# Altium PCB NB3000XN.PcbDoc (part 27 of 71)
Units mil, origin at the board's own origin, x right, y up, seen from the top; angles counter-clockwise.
Board outline 9527.56 x 6929.77 mil, 6 copper layers (Top Layer, GND+SHIELD, MidLayer1, MidLayer2, P2 - 3V3+5V0, Bottom Layer), stack 62.375 mil thick; 832 components, 1027 nets, 4655 pads, 4981 vias.
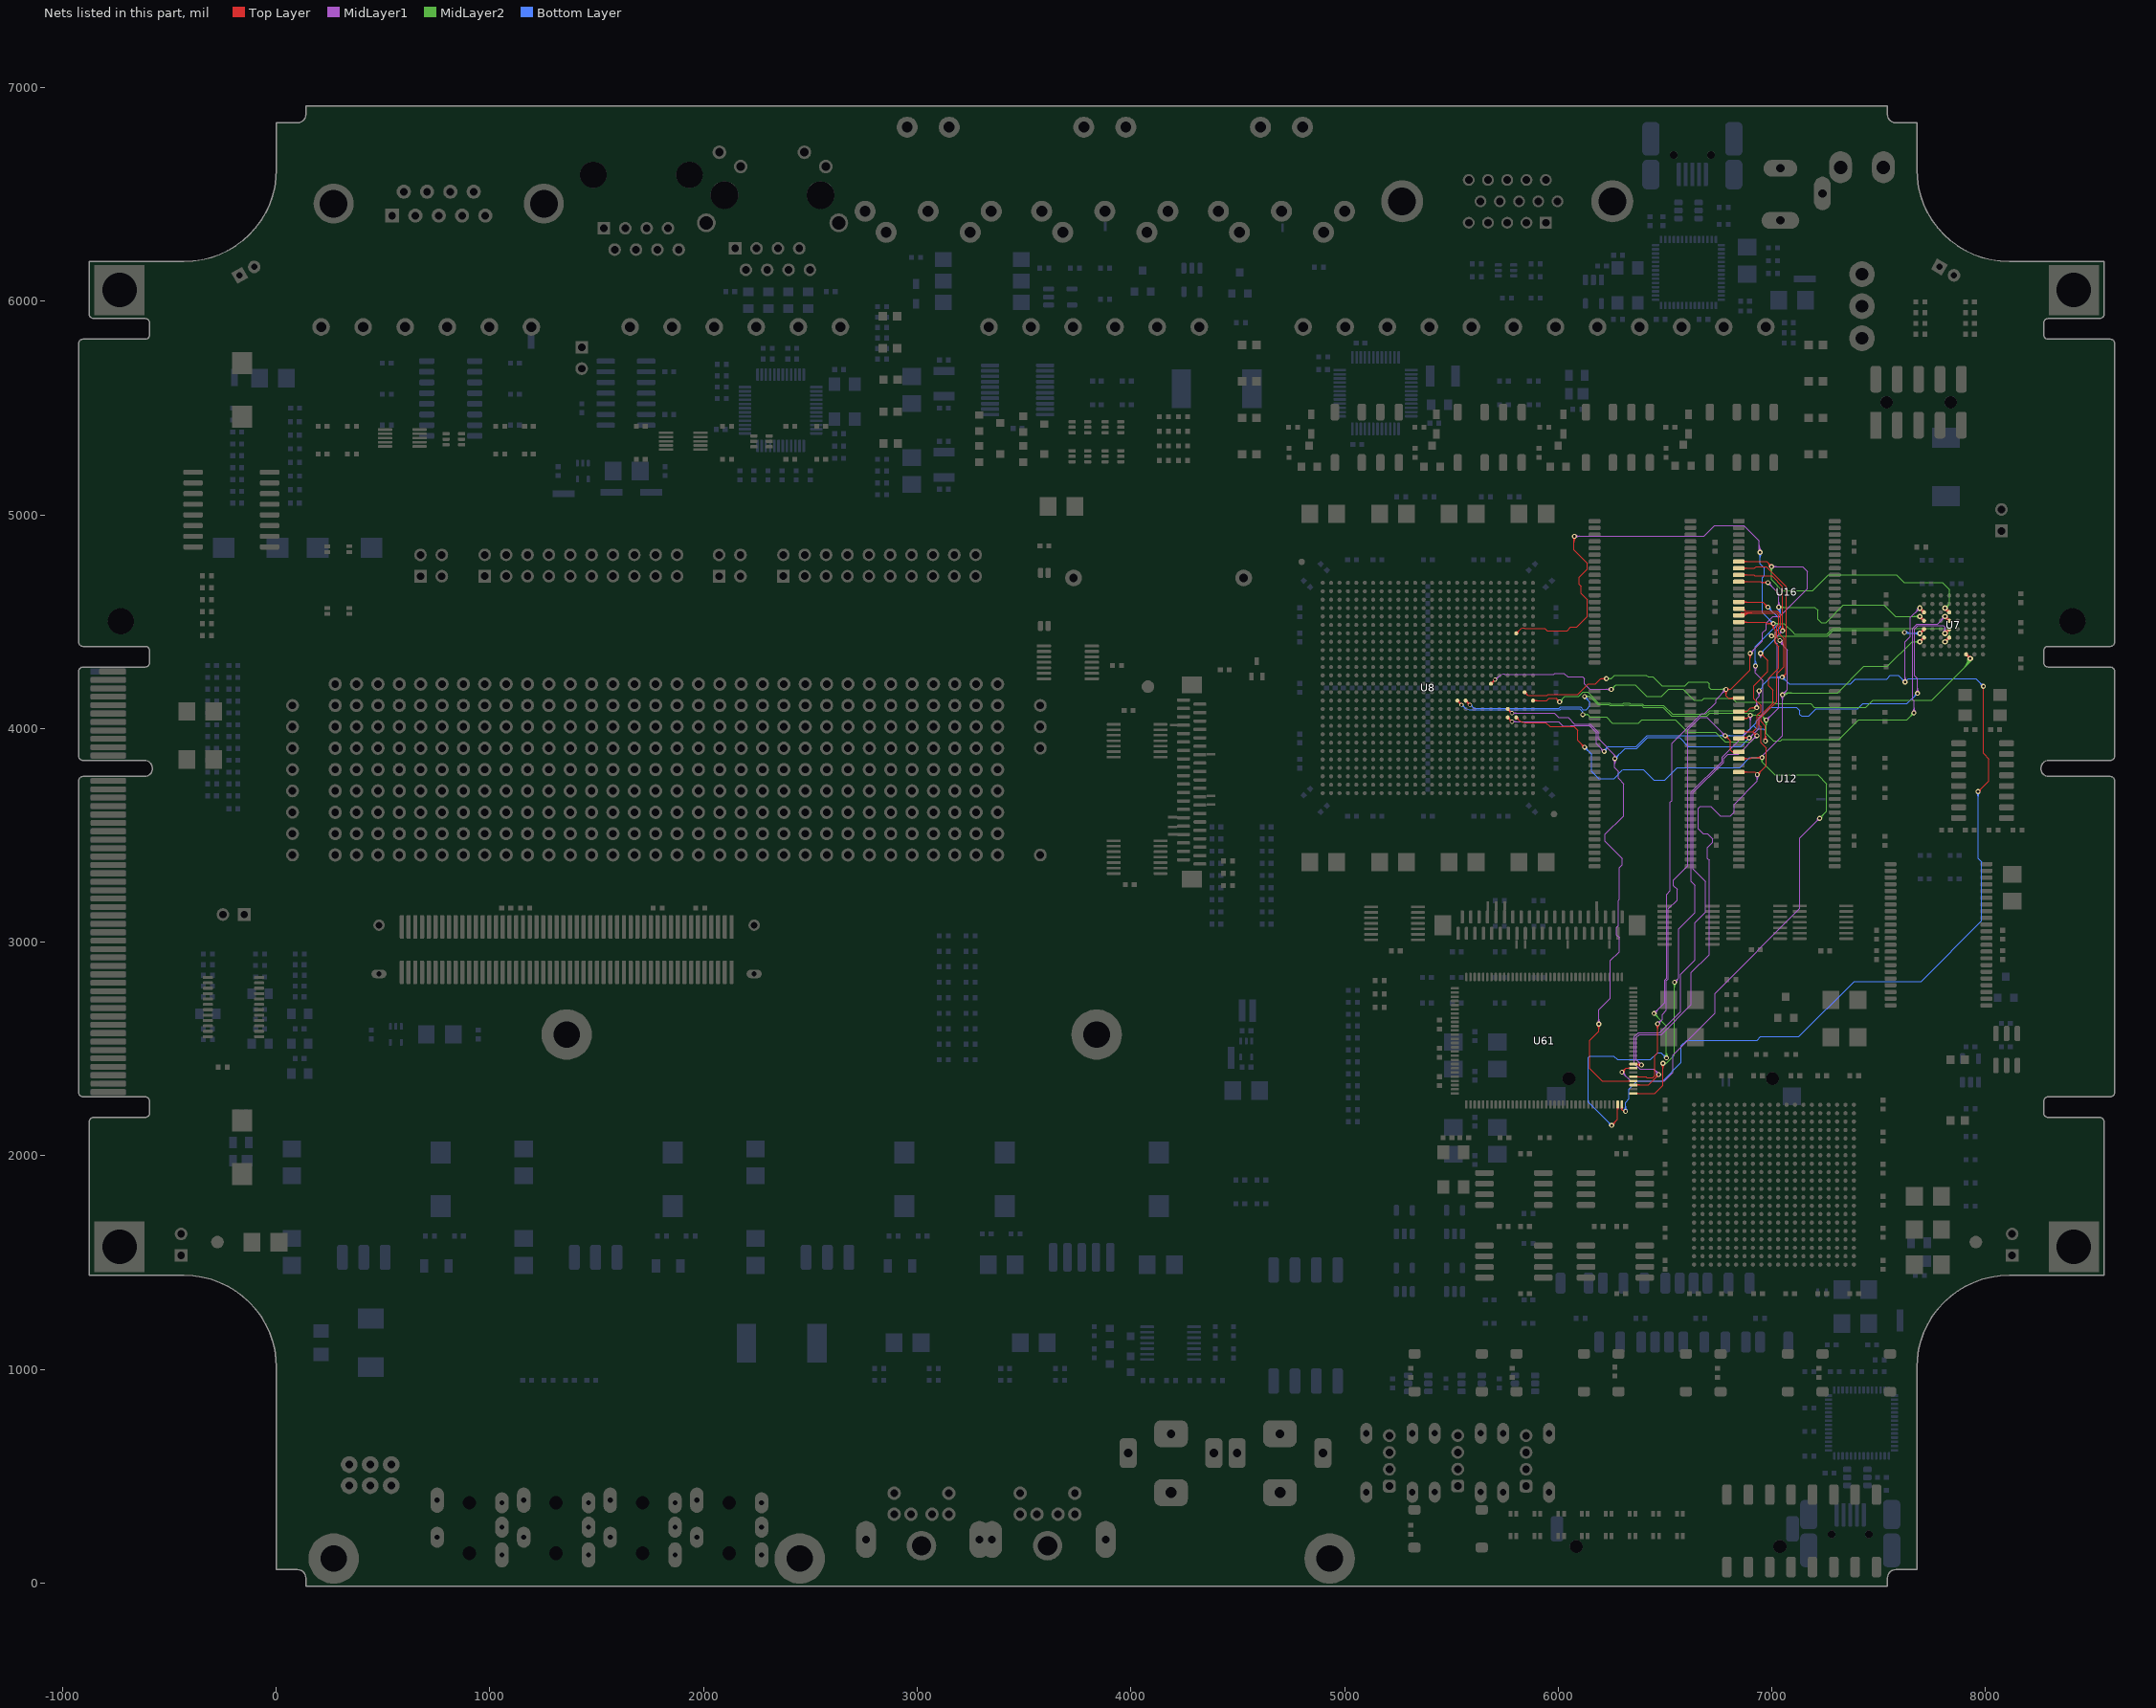
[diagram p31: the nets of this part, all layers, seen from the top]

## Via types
v1: diameter 23, hole 11.81, Top Layer to Bottom Layer, 3672 vias
v2: diameter 26, hole 11.81, Top Layer to Bottom Layer, 461 vias
v3: diameter 19, hole 11.81, Top Layer to Bottom Layer, tented both sides, 396 vias
v4: diameter 23.62, hole 11.81, Top Layer to Bottom Layer, 288 vias
v5: diameter 20, hole 11.81, Top Layer to Bottom Layer, 91 vias
v6: diameter 23, hole 11.81, Top Layer to Bottom Layer, tented both sides, 50 vias
v7: diameter 31, hole 11.81, Top Layer to Bottom Layer, 15 vias
v8: diameter 27.56, hole 11.81, Top Layer to Bottom Layer, tented both sides, 4 vias
v9: diameter 29, hole 11.81, Top Layer to Bottom Layer, 3 vias
v10: diameter 21, hole 11.81, Top Layer to Bottom Layer, 1 vias

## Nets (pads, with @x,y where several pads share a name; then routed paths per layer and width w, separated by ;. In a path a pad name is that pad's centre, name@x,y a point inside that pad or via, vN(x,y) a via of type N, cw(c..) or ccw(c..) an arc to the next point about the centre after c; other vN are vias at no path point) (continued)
DB_MEM.BUS_A24: U7.C8 U8.N21 | length 2990.7
  Top Layer w4: U8.N21@5685.28,4209.69 v3(5704.96,4229.37) ; U8.N21@5685.28,4217.03 ccw(c5685.28,4234.75) 5697.81,4222.22 ccw(c5710.34,4209.69) U8.N21@5692.62,4209.69 ; U8.N21@5685.28,4217.19 ccw(c5685.28,4235.29) 5698.08,4222.49 ccw(c5710.88,4209.69) U8.N21@5692.78,4209.69 ; 5692.16,4216.57 cw(c5704.96,4203.76) 5704.96,4221.87 ccw(c5704.96,4203.76) 5692.16,4216.57 ; 5692.16,4216.57 ccw(c5679.35,4229.37) 5697.46,4229.37 cw(c5679.35,4229.37) 5692.16,4216.57
  Top Layer w8: U7.C8@7909.06,4341.2 cw(c7909.06,4326.72) 7919.3,4336.96 cw(c7929.54,4347.2) U7.C8@7915.06,4347.2 ; U7.C8@7909.06,4347.2 v2(7928.74,4327.52) ; v2@7919.74,4327.52 ccw(c7898.01,4327.52) 7913.38,4342.88 ccw(c7928.74,4358.25) v2@7928.74,4336.52
  MidLayer1 w4: v3@5705.61,4236.84 ccw(c5707.19,4254.88) 5718.83,4241.01 ; v3@5712.43,4228.72 cw(c5730.47,4227.14) 5718.83,4241.01 ; 5781.77,4253.23 5767.84,4253.23 ; v1@6241.81,4176.66 ccw(c6225.59,4160.44) 6225.59,4183.37 ccw(c6225.59,4206.31) v1@6241.81,4190.09 ; v1@6244.64,4179.49 ccw(c6235.25,4170.1) 6235.25,4183.37 ccw(c6235.25,4196.65) v1@6244.64,4187.26 ; v1(6248.52,4183.37) 6148.52,4183.37 6123.52,4208.37 6123.52,4233.37 6115.19,4241.71 6044.19,4241.71 6027.52,4258.37 5985,4258.37 5979.86,4253.23 5920,4253.23 5910,4253.23 5861.38,4253.23 5841.96,4253.23 5767.84,4253.23 ; 5718.83,4241.01 cw(c5748.34,4211.5) 5748.34,4253.23 5767.84,4253.23
  MidLayer2 w4: v1(6248.52,4183.37) 6270.19,4205.04 6360.19,4205.04 6415.19,4150.04 6483.88,4150.04 6517.21,4183.37 6584.84,4183.37 6634.84,4133.37 6656.86,4133.37 6673.52,4133.37 6681.86,4141.71 6815.19,4141.71 6831.86,4125.04 7006.86,4125.04 7015.19,4116.71 7181.86,4116.71 7198.52,4100.04 7440.19,4100.04 7473.52,4133.37 7748.19,4133.37 7930.19,4315.37 7928.86,4316.71 7928.74,4316.71 v2(7928.74,4327.52) ; v1@6248.52,4188.87 ccw(c6248.52,4202.15) 6257.91,4192.76 ccw(c6267.3,4183.37) v1@6254.02,4183.37 ; v1@6248.52,4192.87 ccw(c6248.52,4215.81) 6264.74,4199.59 ccw(c6280.96,4183.37) v1@6258.02,4183.37 ; 7900.35,4285.53 ccw(c7858.36,4327.52) v2@7917.74,4327.52 ; 7907.18,4292.36 ccw(c7872.02,4327.52) v2@7921.74,4327.52 ; 7914.01,4299.19 ccw(c7885.68,4327.52) v2@7925.74,4327.52 ; 7920.83,4306.02 ccw(c7899.33,4327.52) v2@7929.74,4327.52 ; 7927.66,4312.85 ccw(c7912.99,4327.52) v2@7933.74,4327.52
DB_MEM.BUS_D0: U7.E3 U8.P25 U12.2 U16.7 U61.37 | length 7296.9
  Top Layer w4: U8.P25@5842.76,4162.97 cw(c5842.76,4145.25) 5855.29,4157.78 ; U8.P25@5850.1,4170.31 ccw(c5867.83,4170.31) 5855.29,4157.78 ; v1@6218.81,4226.66 ccw(c6202.59,4210.44) 6202.59,4233.37 ccw(c6202.59,4256.31) v1@6218.81,4240.09 ; v1@6221.64,4229.49 ccw(c6212.25,4220.1) 6212.25,4233.37 ccw(c6212.25,4246.65) v1@6221.64,4237.26 ; v1(6225.52,4233.37) 6198.52,4233.37 6173.52,4208.37 6141.52,4208.37 6092.52,4159.37 5953.04,4159.37 5948.47,4154.81 5920,4154.81 5910,4154.81 5862.47,4154.81 cw(c5862.47,4164.96) 5855.29,4157.78 ; v1(6250.52,2142.37) 6278.66,2170.51 U61.37@6278.66,2240 ; v1@6250.52,2147.87 ccw(c6250.52,2161.15) 6259.91,2151.76 ccw(c6269.3,2142.37) v1@6256.02,2142.37 ; v1@6250.52,2151.87 ccw(c6250.52,2174.81) 6266.74,2158.59 ccw(c6282.96,2142.37) v1@6260.02,2142.37 ; U61.37@6275.83,2223.98 cw(c6269,2217.15) 6278.66,2217.15 cw(c6288.32,2217.15) U61.37@6281.49,2223.98 ; v1@6778.47,4176.66 cw(c6762.26,4160.44) 6785.19,4160.44 cw(c6808.13,4160.44) v1@6791.91,4176.66 ; v1@6781.3,4179.49 cw(c6771.91,4170.1) 6785.19,4170.1 cw(c6798.47,4170.1) v1@6789.08,4179.49 ; v1@6789.11,4179.52 cw(c6798.31,4170.47) 6798.31,4183.37 cw(c6798.31,4196.28) v1@6789.11,4187.23 ; v1@6791.96,4176.71 cw(c6807.86,4161.09) 6807.86,4183.37 ; v1@6791.96,4190.04 ccw(c6807.86,4205.66) 6807.86,4183.37 ; U12.2@6822.37,4137.3 ccw(c6808.72,4123.64) 6808.72,4142.95 ccw(c6808.72,4162.27) U12.2@6822.37,4148.61 ; U12.2@6825.61,4142.95 U12.2@6845.59,4142.95 6796.05,4142.95 6785.19,4153.81 v1(6785.19,4183.37) 6807.86,4183.37 ; U16.7@6845.59,4781.73 6975.17,4781.73 v1(6998.52,4758.37) ; U16.7@6868.81,4776.08 cw(c6882.46,4762.42) 6882.46,4781.73 cw(c6882.46,4801.05) U16.7@6868.81,4787.39 ; v1@6891.81,4345.66 cw(c6875.59,4329.44) 6898.52,4329.44 cw(c6921.46,4329.44) v1@6905.24,4345.66 ; v1@6894.64,4348.49 cw(c6885.25,4339.1) 6898.52,4339.1 cw(c6911.8,4339.1) v1@6902.41,4348.49 ; v1(6898.52,4352.37) 6898.52,4274.04 6807.86,4183.37 ; v1@6989.02,4758.37 ccw(c6966.09,4758.37) 6982.31,4774.59 ccw(c6998.52,4790.81) v1@6998.52,4767.87 ; v1@6993.02,4758.37 ccw(c6979.75,4758.37) 6989.14,4767.76 ccw(c6998.52,4777.15) v1@6998.52,4763.87
  Top Layer w8: v2@7810.63,4554.74 cw(c7810.63,4533.01) 7825.99,4548.38 cw(c7841.36,4563.74) v2@7819.63,4563.74 ; v2(7810.63,4563.74) U7.E3@7830.32,4544.06 ; U7.E3@7824.32,4544.06 ccw(c7809.83,4544.06) 7820.07,4554.3 ccw(c7830.32,4564.54) U7.E3@7830.32,4550.06
  MidLayer1 w4: v1(6448.52,2666.71) 6498.52,2716.71 6498.52,2822.67 6507.19,2831.34 6507.19,3224.41 6523.52,3240.75 6523.52,3654.79 ; v1@6448.52,2672.21 ccw(c6448.52,2685.49) 6457.91,2676.1 ccw(c6467.3,2666.71) v1@6454.02,2666.71 ; v1@6448.52,2676.21 ccw(c6448.52,2699.14) 6464.74,2682.93 ccw(c6480.96,2666.71) v1@6458.02,2666.71 ; 6530,3661.26 6523.52,3654.79 ; v1@6775.69,4183.37 cw(c6752.76,4183.37) 6768.97,4167.16 cw(c6785.19,4150.94) v1@6785.19,4173.87 ; v1@6779.69,4183.37 cw(c6766.41,4183.37) 6775.8,4173.99 cw(c6785.19,4164.6) v1@6785.19,4177.87 ; v1(6785.19,4183.37) 6737.87,4136.06 6737.87,4122.72 6685.15,4070 6671.5,4070 6531.86,3930.36 6531.86,3663.12 6523.52,3654.79 ; v1(6898.52,4352.37) 6956.86,4410.71 6956.86,4448.37 6973.52,4465.04 6973.52,4492.71 7005.86,4525.04 7037.19,4525.04 7166.52,4654.37 7166.52,4735.37 7143.52,4758.37 v1(6998.52,4758.37) ; v1@6898.52,4357.87 ccw(c6898.52,4371.15) 6907.91,4361.76 ccw(c6917.3,4352.37) v1@6904.02,4352.37 ; v1@6898.52,4361.87 ccw(c6898.52,4384.81) 6914.74,4368.59 ccw(c6930.96,4352.37) v1@6908.02,4352.37 ; v1@7002.41,4754.49 cw(c7011.8,4745.1) 7011.8,4758.37 cw(c7011.8,4771.65) v1@7002.41,4762.26 ; v1@7005.24,4751.66 cw(c7021.46,4735.44) 7021.46,4758.37 cw(c7021.46,4781.31) v1@7005.24,4765.09
  MidLayer2 w4: v1(6225.52,4233.37) 6248.52,4233.37 6265.19,4250.04 6411.6,4250.04 6419.94,4241.71 6444.19,4241.71 6486.52,4199.37 6593.5,4199.37 6612.17,4218.04 6698.52,4218.04 6706.86,4209.71 6706.86,4191.71 6715.19,4183.37 v1(6785.19,4183.37) ; v1@6229.41,4229.49 cw(c6238.8,4220.1) 6238.8,4233.37 cw(c6238.8,4246.65) v1@6229.41,4237.26 ; v1@6232.24,4226.66 cw(c6248.46,4210.44) 6248.46,4233.37 cw(c6248.46,4256.31) v1@6232.24,4240.09 ; v1@6448.52,2657.21 cw(c6448.52,2634.27) 6464.74,2650.49 cw(c6480.96,2666.71) v1@6458.02,2666.71 ; v1@6448.52,2661.21 cw(c6448.52,2647.93) 6457.91,2657.32 cw(c6467.3,2666.71) v1@6454.02,2666.71 ; v1(6448.52,2666.71) 6506.86,2608.37 v1(6506.86,2458.37) ; v1@6500.14,2465.09 ccw(c6483.92,2481.31) 6506.86,2481.31 ccw(c6529.79,2481.31) v1@6513.57,2465.09 ; v1@6502.97,2462.26 ccw(c6493.58,2471.65) 6506.86,2471.65 ccw(c6520.14,2471.65) v1@6510.75,2462.26 ; v1@6778.47,4176.66 ccw(c6762.26,4160.44) 6762.26,4183.37 ccw(c6762.26,4206.31) v1@6778.47,4190.09 ; v1@6781.3,4179.49 ccw(c6771.91,4170.1) 6771.91,4183.37 ccw(c6771.91,4196.65) v1@6781.3,4187.26 ; v1@6991.81,4751.66 cw(c6975.59,4735.44) 6998.52,4735.44 cw(c7021.46,4735.44) v1@7005.24,4751.66 ; v1@6994.64,4754.49 cw(c6985.25,4745.1) 6998.52,4745.1 cw(c7011.8,4745.1) v1@7002.41,4754.49 ; v1(6998.52,4758.37) 6998.52,4696.48 7048.96,4646.04 7191.04,4646.04 7265,4720 7582.54,4720 7619.17,4683.37 7798.52,4683.37 7831.86,4650.04 7831.86,4584.97 7818.27,4571.37 7810.63,4571.37 v2(7810.63,4563.74) ; v2@7810.63,4570.74 ccw(c7810.63,4587.64) 7822.58,4575.69 ccw(c7834.53,4563.74) v2@7817.63,4563.74 ; v2@7810.63,4574.74 ccw(c7810.63,4601.3) 7829.41,4582.52 ccw(c7848.19,4563.74) v2@7821.63,4563.74
  Bottom Layer w4: v1@6241.02,2142.37 ccw(c6218.09,2142.37) 6234.31,2158.59 ccw(c6250.52,2174.81) v1@6250.52,2151.87 ; v1@6245.02,2142.37 ccw(c6231.75,2142.37) 6241.14,2151.76 ccw(c6250.52,2161.15) v1@6250.52,2147.87 ; v1(6250.52,2142.37) 6140.19,2252.71 6140.19,2395 6140.19,2400.04 6140.19,2460.19 6146.71,2466.71 6206.86,2466.71 6260.54,2466.71 6277.21,2450.04 6431.86,2450.04 6465.19,2483.37 6481.86,2483.37 v1(6506.86,2458.37) ; v1@6497.36,2458.37 ccw(c6474.42,2458.37) 6490.64,2474.59 ccw(c6506.86,2490.81) v1@6506.86,2467.87 ; v1@6501.36,2458.37 ccw(c6488.08,2458.37) 6497.47,2467.76 ccw(c6506.86,2477.15) v1@6506.86,2463.87
DB_MEM.BUS_D1: U7.H3 U8.R26 U12.4 U16.8 U61.38 | length 7924
  Top Layer w4: U8.R26@5882.13,4130.94 5910,4130.94 5920,4130.94 5947.24,4130.94 5958,4141.71 5990.19,4141.71 v1(6006.86,4125.04) ; U8.R26@5887.32,4125.75 cw(c5899.85,4113.22) 5899.85,4130.94 cw(c5899.85,4148.67) U8.R26@5887.32,4136.14 ; U8.R26@5887.43,4125.64 cw(c5900.23,4112.84) 5900.23,4130.94 cw(c5900.23,4149.05) U8.R26@5887.43,4136.25 ; v1@5997.36,4125.04 ccw(c5974.42,4125.04) 5990.64,4141.26 ccw(c6006.86,4157.48) v1@6006.86,4134.54 ; v1@6001.36,4125.04 ccw(c5988.08,4125.04) 5997.47,4134.43 ccw(c6006.86,4143.82) v1@6006.86,4130.54 ; U61.38@6295.52,2223.98 cw(c6288.69,2217.15) 6298.35,2217.15 cw(c6308,2217.15) U61.38@6301.17,2223.98 ; U61.38@6298.34,2240 6298.35,2216.37 6306.35,2208.37 v1(6315.19,2208.37) ; U12.4@6845.59,4079.96 6882.6,4079.96 6900.02,4097.37 v1(6929.52,4097.37) ; U16.8@6845.59,4750.24 6918.39,4750.24 6926.52,4758.37 6973.52,4758.37 7068.86,4663.04 7068.86,4433.37 7065.19,4429.71 7065.19,4257.37 v1(7048.52,4240.71) ; U12.4@6868.81,4074.3 cw(c6882.46,4060.65) 6882.46,4079.96 cw(c6882.46,4099.27) U12.4@6868.81,4085.62 ; U16.8@6868.81,4744.58 cw(c6882.46,4730.92) 6882.46,4750.24 cw(c6882.46,4769.55) U16.8@6868.81,4755.89 ; v1@6922.81,4090.66 ccw(c6906.59,4074.44) 6906.59,4097.37 ccw(c6906.59,4120.31) v1@6922.81,4104.09 ; v1@6925.64,4093.49 ccw(c6916.25,4084.1) 6916.25,4097.37 ccw(c6916.25,4110.65) v1@6925.64,4101.26 ; v1@7048.52,4246.21 ccw(c7048.52,4259.49) 7057.91,4250.1 ccw(c7067.3,4240.71) v1@7054.02,4240.71 ; v1@7048.52,4250.21 ccw(c7048.52,4273.14) 7064.74,4256.93 ccw(c7080.96,4240.71) v1@7058.02,4240.71 ; v1(7965.19,3705.37) 8015.19,3755.37 8015.19,3858.37 7990.19,3883.37 v1(7990.19,4198.04) ; v1@7965.19,3710.87 ccw(c7965.19,3724.15) 7974.58,3714.76 ccw(c7983.97,3705.37) v1@7970.69,3705.37 ; v1@7965.19,3714.87 ccw(c7965.19,3737.81) 7981.41,3721.59 ccw(c7997.63,3705.37) v1@7974.69,3705.37
  Top Layer w8: v2@7692.52,4554.74 cw(c7692.52,4533.01) 7707.88,4548.38 cw(c7723.25,4563.74) v2@7701.52,4563.74 ; v2(7692.52,4563.74) U7.H3@7712.2,4544.06 ; U7.H3@7706.2,4544.06 ccw(c7691.72,4544.06) 7701.96,4554.3 ccw(c7712.2,4564.54) U7.H3@7712.2,4550.06
  MidLayer1 w4: v1@6922.81,4104.09 ccw(c6906.59,4120.31) 6929.52,4120.31 ccw(c6952.46,4120.31) v1@6936.24,4104.09 ; v1@6925.64,4101.26 ccw(c6916.25,4110.65) 6929.52,4110.65 ccw(c6942.8,4110.65) v1@6933.41,4101.26 ; v1(6929.52,4097.37) 6929.52,4139.52 6940,4150 ; v1@6933.47,4169.99 cw(c6917.26,4153.77) 6940.19,4153.77 cw(c6963.13,4153.77) v1@6946.91,4169.99 ; v1@6936.3,4172.82 cw(c6926.91,4163.43) 6940.19,4163.43 cw(c6953.47,4163.43) v1@6944.08,4172.82 ; 6940.19,4150 v1(6940.19,4176.71) ; v1@7616.81,4224.43 ccw(c7600.59,4240.64) 7623.52,4240.64 ccw(c7646.46,4240.64) v1@7630.24,4224.43 ; v1@7619.64,4221.6 ccw(c7610.25,4230.99) 7623.52,4230.99 ccw(c7636.8,4230.99) v1@7627.41,4221.6 ; v1(7623.52,4217.71) 7623.52,4405.39 7648.52,4430.39 7648.52,4519.74 v2(7692.52,4563.74) ; v2@7681.52,4563.74 cw(c7654.96,4563.74) 7673.74,4544.96 cw(c7692.52,4526.19) v2@7692.52,4552.74 ; v2@7685.52,4563.74 cw(c7668.62,4563.74) 7680.57,4551.79 cw(c7692.52,4539.84) v2@7692.52,4556.74
  MidLayer2 w4: v1(6006.86,4125.04) 6031.86,4150.04 6095.52,4150.04 6115.48,4170 6138.23,4170 6188.52,4119.71 6241.48,4119.71 6245.82,4115.37 6302.56,4115.37 6306,4118.81 6334,4118.81 6337.44,4115.37 6394.5,4115.37 6401.5,4108.38 6493.16,4108.38 6534.17,4067.37 6692.86,4067.37 6708.86,4083.37 6915.52,4083.37 v1(6929.52,4097.37) ; v1@6006.86,4130.54 ccw(c6006.86,4143.82) 6016.25,4134.43 ccw(c6025.64,4125.04) v1@6012.36,4125.04 ; v1@6006.86,4134.54 ccw(c6006.86,4157.48) 6023.07,4141.26 ccw(c6039.29,4125.04) v1@6016.36,4125.04
  Bottom Layer w4: v1@6308.47,2215.09 ccw(c6292.26,2231.31) 6315.19,2231.31 ccw(c6338.13,2231.31) v1@6321.91,2215.09 ; v1@6311.3,2212.26 ccw(c6301.91,2221.65) 6315.19,2221.65 ccw(c6328.47,2221.65) v1@6319.08,2212.26 ; v1(6315.19,2208.37) 6315.19,2250 6332.19,2267 6332.19,2312.19 6370.04,2350.04 6489.58,2350.04 6576.18,2436.64 6576.18,2516.38 6601.51,2541.71 6930.52,2541.71 6947.19,2558.37 7126.86,2558.37 7385.19,2816.71 7698.52,2816.71 7981.86,3100.04 7981.86,3376.04 7965.19,3392.71 v1(7965.19,3705.37) ; v1(6940.19,4176.71) 6955.75,4192.27 6955.75,4202.62 6993.84,4240.71 v1(7048.52,4240.71) 7080.86,4208.37 7367.54,4208.37 7391.54,4232.37 7537.33,4232.37 7555,4250.04 7591.19,4250.04 v1(7623.52,4217.71) 7639.19,4233.37 7954.86,4233.37 v1(7990.19,4198.04) ; v1@7041.81,4233.99 ccw(c7025.59,4217.77) 7025.59,4240.71 ccw(c7025.59,4263.64) v1@7041.81,4247.43 ; v1@7044.64,4236.82 ccw(c7035.25,4227.43) 7035.25,4240.71 ccw(c7035.25,4253.99) v1@7044.64,4244.6 ; v1@7048.52,4231.21 cw(c7048.52,4208.27) 7064.74,4224.49 cw(c7080.96,4240.71) v1@7058.02,4240.71 ; v1@7048.52,4235.21 cw(c7048.52,4221.93) 7057.91,4231.32 cw(c7067.3,4240.71) v1@7054.02,4240.71 ; v1@7614.02,4217.71 ccw(c7591.09,4217.71) 7607.31,4233.93 ccw(c7623.52,4250.14) v1@7623.52,4227.21 ; v1@7618.02,4217.71 ccw(c7604.75,4217.71) 7614.13,4227.1 ccw(c7623.52,4236.49) v1@7623.52,4223.21 ; v1@7958.47,3698.66 cw(c7942.26,3682.44) 7965.19,3682.44 cw(c7988.13,3682.44) v1@7971.91,3698.66 ; v1@7961.3,3701.49 cw(c7951.91,3692.1) 7965.19,3692.1 cw(c7978.47,3692.1) v1@7969.08,3701.49 ; v1@7980.69,4198.04 ccw(c7957.76,4198.04) 7973.97,4214.26 ccw(c7990.19,4230.48) v1@7990.19,4207.54 ; v1@7984.69,4198.04 ccw(c7971.41,4198.04) 7980.8,4207.43 ccw(c7990.19,4216.82) v1@7990.19,4203.54
DB_MEM.BUS_D2: U7.E4 U8.R18 U12.5 U16.9 U61.39 | length 7174.9
  Top Layer w4: U8.R18@5567.17,4123.44 cw(c5567.17,4105.34) 5579.97,4118.14 cw(c5592.77,4130.94) U8.R18@5574.67,4130.94 ; U8.R18@5567.17,4123.6 cw(c5567.17,4105.88) 5579.7,4118.41 cw(c5592.23,4130.94) U8.R18@5574.51,4130.94 ; U8.R18@5567.17,4130.94 v3(5586.85,4111.26) ; U61.39@6351.93,2291.98 6451.19,2291.98 6490.19,2330.98 v1(6490.19,2433.37) ; U61.39@6367.95,2289.15 cw(c6374.78,2282.32) 6374.78,2291.98 cw(c6374.78,2301.63) U61.39@6367.95,2294.8 ; v1@6483.47,2426.66 cw(c6467.26,2410.44) 6490.19,2410.44 cw(c6513.13,2410.44) v1@6496.91,2426.66 ; v1@6486.3,2429.49 cw(c6476.91,2420.1) 6490.19,2420.1 cw(c6503.47,2420.1) v1@6494.08,2429.49 ; U12.5@6845.59,4048.46 6885.28,4048.46 v1(6899.19,4062.37) ; U16.9@6845.59,4718.74 6915.52,4718.74 6919.52,4714.74 7000.49,4714.74 7050.86,4664.37 v1(7050.86,4458.37) ; U12.5@6868.81,4042.81 cw(c6882.46,4029.15) 6882.46,4048.46 cw(c6882.47,4067.78) U12.5@6868.81,4054.12 ; U16.9@6868.81,4713.08 cw(c6882.46,4699.43) 6882.46,4718.74 cw(c6882.46,4738.05) U16.9@6868.81,4724.4 ; v1@7044.14,4465.09 ccw(c7027.92,4481.31) 7050.86,4481.31 ccw(c7073.79,4481.31) v1@7057.57,4465.09 ; v1@7046.97,4462.26 ccw(c7037.58,4471.65) 7050.86,4471.65 ccw(c7064.14,4471.65) v1@7054.75,4462.26 ; 5574.05,4124.06 cw(c5561.24,4111.26) 5579.35,4111.26 ccw(c5561.24,4111.26) 5574.05,4124.06 ; 5574.05,4124.06 ccw(c5586.85,4136.87) 5586.85,4118.76 cw(c5586.85,4136.87) 5574.05,4124.06
  Top Layer w8: v2@7810.63,4515.37 cw(c7810.63,4493.64) 7825.99,4509.01 cw(c7841.36,4524.37) v2@7819.63,4524.37 ; v2(7810.63,4524.37) U7.E4@7830.32,4504.69 ; U7.E4@7824.32,4504.69 ccw(c7809.83,4504.69) 7820.07,4514.93 ccw(c7830.32,4525.17) U7.E4@7830.32,4510.69
  MidLayer1 w4: v1(6544.86,2813.04) 6561.71,2829.89 6564.86,2833.04 6564.86,3063 6640.19,3138.33 6640.19,3266.71 6623.52,3283.37 6623.52,3702.67 6767,3846.15 6767,3867 6899.19,3999.19 v1(6899.19,4062.37) ; v1@6544.86,2818.54 ccw(c6544.86,2831.82) 6554.25,2822.43 ccw(c6563.64,2813.04) v1@6550.36,2813.04 ; v1@6544.86,2822.54 ccw(c6544.86,2845.48) 6561.07,2829.26 ccw(c6577.29,2813.04) v1@6554.36,2813.04 ; v1@6892.47,4055.66 cw(c6876.26,4039.44) 6899.19,4039.44 cw(c6922.13,4039.44) v1@6905.91,4055.66 ; v1@6895.3,4058.49 cw(c6885.91,4049.1) 6899.19,4049.1 cw(c6912.47,4049.1) v1@6903.08,4058.49 ; v1(6973.52,4039.71) 7031.86,4098.04 7031.86,4233.37 7025.19,4240.04 7025.19,4396.04 7015.19,4406.04 7015.19,4422.71 v1(7050.86,4458.37) ; v1@6973.52,4045.21 ccw(c6973.52,4058.49) 6982.91,4049.1 ccw(c6992.3,4039.71) v1@6979.02,4039.71 ; v1@6973.52,4049.21 ccw(c6973.52,4072.14) 6989.74,4055.93 ccw(c7005.96,4039.71) v1@6983.02,4039.71 ; v1@7041.36,4458.37 cw(c7018.42,4458.37) 7034.64,4442.16 cw(c7050.86,4425.94) v1@7050.86,4448.87 ; v1@7045.36,4458.37 cw(c7032.08,4458.37) 7041.47,4448.99 cw(c7050.86,4439.6) v1@7050.86,4452.87 ; v1@7658.47,4080.09 ccw(c7642.26,4096.31) 7665.19,4096.31 ccw(c7688.13,4096.31) v1@7671.91,4080.09 ; v1@7661.3,4077.26 ccw(c7651.91,4086.65) 7665.19,4086.65 ccw(c7678.47,4086.65) v1@7669.08,4077.26 ; v1(7665.19,4073.37) 7665.19,4129.81 7660,4135 7660,4469.85 7679.97,4489.82 7776.08,4489.82 v2(7810.63,4524.37) ; v2@7799.63,4524.37 cw(c7773.07,4524.37) 7791.85,4505.59 cw(c7810.63,4486.82) v2@7810.63,4513.37 ; v2@7803.63,4524.37 cw(c7786.73,4524.37) 7798.68,4512.42 cw(c7810.63,4500.47) v2@7810.63,4517.37
  MidLayer2 w4: v1(6123.52,4150.04) 6146.88,4150.04 6185.21,4111.71 6238.17,4111.71 6242.5,4107.37 6305.87,4107.37 6309.31,4110.81 6330.69,4110.81 6334.13,4107.37 6391.19,4107.37 6398.18,4100.38 6489.85,4100.38 6530.86,4059.37 6697.19,4059.37 6709.86,4072.04 6889.52,4072.04 v1(6899.19,4062.37) 6950.86,4062.37 v1(6973.52,4039.71) 6973.52,3975.04 7006.86,3941.71 7040.19,3941.71 7048.52,3950.04 7314.58,3950.04 7405.92,4041.37 7633.19,4041.37 7641.86,4050.04 v1(7665.19,4073.37) ; v1@6127.41,4146.15 cw(c6136.8,4136.76) 6136.8,4150.04 cw(c6136.8,4163.32) v1@6127.41,4153.93 ; v1@6130.24,4143.32 cw(c6146.46,4127.11) 6146.46,4150.04 cw(c6146.46,4172.98) v1@6130.24,4156.76 ; v1(6490.19,2433.37) 6506.86,2433.37 ; v1@6498.36,2428.53 cw(c6506.86,2423.51) 6506.86,2433.37 ; v1@6498.36,2438.22 ccw(c6506.86,2443.24) 6506.86,2433.37 ; v1@6538.14,2806.32 cw(c6521.92,2790.11) 6544.86,2790.11 cw(c6567.79,2790.11) v1@6551.57,2806.32 ; v1@6540.97,2809.15 cw(c6531.58,2799.76) 6544.86,2799.76 cw(c6558.14,2799.76) v1@6548.75,2809.15 ; v1(6544.86,2813.04) 6544.86,2471.37 6506.86,2433.37 ; v1@6903.08,4058.49 cw(c6912.47,4049.1) 6912.47,4062.37 cw(c6912.47,4075.65) v1@6903.08,4066.26 ; v1@6905.91,4055.66 cw(c6922.13,4039.44) 6922.13,4062.37 cw(c6922.13,4085.31) v1@6905.91,4069.09 ; v1@6964.02,4039.71 ccw(c6941.09,4039.71) 6957.31,4055.93 ccw(c6973.52,4072.14) v1@6973.52,4049.21 ; v1@6966.81,4032.99 cw(c6950.59,4016.77) 6973.52,4016.77 cw(c6996.46,4016.77) v1@6980.24,4032.99 ; v1@6968.02,4039.71 ccw(c6954.75,4039.71) 6964.14,4049.1 ccw(c6973.52,4058.49) v1@6973.52,4045.21 ; v1@6969.64,4035.82 cw(c6960.25,4026.43) 6973.52,4026.43 cw(c6986.8,4026.43) v1@6977.41,4035.82 ; v1@7655.69,4073.37 cw(c7632.76,4073.37) 7648.97,4057.16 cw(c7665.19,4040.94) v1@7665.19,4063.87 ; v1@7659.69,4073.37 cw(c7646.41,4073.37) 7655.8,4063.99 cw(c7665.19,4054.6) v1@7665.19,4067.87
  Bottom Layer w4: v3@5587.5,4103.79 cw(c5589.08,4085.75) 5600.72,4099.62 cw(c5612.36,4113.49) v3@5594.32,4111.91 ; 5600.43,4099.87 ccw(c5610.36,4109.8) 5610.36,4095.75 5703.9,4095.75 5910,4095.75 5920,4095.75 6005.15,4095.75 6010.21,4100.81 6105.09,4100.81 6116.87,4089.02 6131.84,4089.02 6133.58,4090.77 6148.52,4105.71 6148.52,4125.04 v1(6123.52,4150.04) ; v1@6123.52,4140.54 cw(c6123.52,4117.61) 6139.74,4133.82 cw(c6155.96,4150.04) v1@6133.02,4150.04 ; v1@6123.52,4144.54 cw(c6123.52,4131.26) 6132.91,4140.65 cw(c6142.3,4150.04) v1@6129.02,4150.04
DB_MEM.BUS_D3: U7.H4 U8.R17 U12.7 U16.10 U61.41 | length 6741.8
  Top Layer w4: U8.R17@5527.8,4123.44 cw(c5527.8,4105.34) 5540.6,4118.14 cw(c5553.4,4130.94) U8.R17@5535.3,4130.94 ; U8.R17@5527.8,4123.6 cw(c5527.8,4105.88) 5540.33,4118.41 cw(c5552.86,4130.94) U8.R17@5535.14,4130.94 ; U8.R17@5527.8,4130.94 v3(5547.48,4111.26) ; U61.41@6356.86,2333.37 6423.52,2333.37 v1(6470.52,2380.37) ; U61.41@6367.95,2328.52 cw(c6379.68,2316.79) 6379.68,2333.37 ; v1@6461.02,2380.37 cw(c6438.09,2380.37) 6454.31,2364.16 cw(c6470.52,2347.94) v1@6470.52,2370.87 ; v1@6465.02,2380.37 cw(c6451.75,2380.37) 6461.14,2370.99 cw(c6470.52,2361.6) v1@6470.52,2374.87 ; U12.7@6845.59,3985.47 6911.52,3985.47 ; U16.10@6845.59,4687.24 6946.66,4687.24 6950.52,4683.37 v1(6981.86,4683.37) ; U12.7@6868.81,3979.82 cw(c6882.46,3966.16) 6882.46,3985.47 cw(c6882.46,4004.79) U12.7@6868.81,3991.13 ; U16.10@6868.81,4681.59 cw(c6882.46,4667.93) 6882.46,4687.24 cw(c6882.46,4706.56) U16.10@6868.81,4692.9 ; 6913.9,3983.09 cw(c6897.52,3966.71) v1@6920.69,3966.71 ; 6914.14,3982.86 ccw(c6930.19,3998.91) v1@6930.19,3976.21 ; v1@6930.19,3966.8 6911.52,3985.47 ; v1@6947.19,4342.87 cw(c6947.19,4319.94) 6963.41,4336.16 cw(c6979.63,4352.37) v1@6956.69,4352.37 ; v1@6947.19,4346.87 cw(c6947.19,4333.6) 6956.58,4342.99 cw(c6965.97,4352.37) v1@6952.69,4352.37 ; v1(6947.19,4352.37) 6981.86,4317.71 6981.86,4266.71 6915.19,4200.04 6915.19,4140.71 6948.52,4107.37 6948.52,4079.71 6931.86,4063.04 6931.86,4005.8 6911.52,3985.47 ; v1@6975.14,4676.66 ccw(c6958.92,4660.44) 6958.92,4683.37 ccw(c6958.92,4706.31) v1@6975.14,4690.09 ; v1@6977.97,4679.49 ccw(c6968.58,4670.1) 6968.58,4683.37 ccw(c6968.58,4696.65) v1@6977.97,4687.26 ; 5534.68,4124.06 cw(c5521.87,4111.26) 5539.98,4111.26 ccw(c5521.87,4111.26) 5534.68,4124.06 ; 5534.68,4124.06 ccw(c5547.48,4136.87) 5547.48,4118.76 cw(c5547.48,4136.87) 5534.68,4124.06 ; 6920.73,3976.26 cw(c6911.18,3966.71) 6924.69,3966.71 ccw(c6911.18,3966.71) 6920.73,3976.26 ; 6920.97,3976.03 ccw(c6930.19,3985.25) 6930.19,3972.21 cw(c6930.19,3985.25) 6920.97,3976.03
  Top Layer w8: v2@7692.52,4515.37 cw(c7692.52,4493.64) 7707.88,4509.01 cw(c7723.25,4524.37) v2@7701.52,4524.37 ; v2(7692.52,4524.37) U7.H4@7712.2,4504.69 ; U7.H4@7706.2,4504.69 ccw(c7691.72,4504.69) 7701.96,4514.93 ccw(c7712.2,4525.17) U7.H4@7712.2,4510.69
  MidLayer1 w4: 6451.01,2404.56 cw(c6426.82,2380.37) v1@6461.02,2380.37 ; 6457.84,2397.73 cw(c6440.48,2380.37) v1@6465.02,2380.37 ; 6462.27,2393.29 ccw(c6470.52,2401.55) v1@6470.52,2389.87 ; 6464.66,2390.9 cw(c6454.14,2380.37) v1@6469.02,2380.37 ; v1@6470.52,2385.04 6448.52,2407.04 6381.86,2407.04 6356.86,2432.04 6356.86,2557.56 6375,2575.71 6474.19,2575.71 6573.52,2675.04 6573.52,2850.04 6640.19,2916.71 6640.19,3091.71 6690.19,3141.71 6690.19,3283.37 6631.86,3341.71 6631.86,3699.69 6775,3842.83 6775,3860 6795,3880 6843.48,3880 v1(6930.19,3966.71) ; v1@6920.69,3966.71 cw(c6897.76,3966.71) 6913.97,3950.49 cw(c6930.19,3934.27) v1@6930.19,3957.21 ; v1@6924.69,3966.71 cw(c6911.41,3966.71) 6920.8,3957.32 cw(c6930.19,3947.93) v1@6930.19,3961.21 ; v1@6941.14,4345.05 cw(c6930.5,4332.19) 6947.19,4332.19 cw(c6963.88,4332.19) v1@6953.24,4345.05 ; v1@6943.69,4348.14 cw(c6937.53,4340.69) 6947.19,4340.69 cw(c6956.85,4340.69) v1@6950.7,4348.14 ; v1@6981.86,4673.87 cw(c6981.86,4650.94) 6998.07,4667.16 cw(c7014.29,4683.37) v1@6991.36,4683.37 ; v1@6981.86,4677.87 cw(c6981.86,4664.6) 6991.25,4673.99 cw(c7000.64,4683.37) v1@6987.36,4683.37 ; v1(6981.86,4683.37) 7032.52,4632.71 v1(7032.52,4568.37) ; v1@7025.81,4575.09 ccw(c7009.59,4591.31) 7032.52,4591.31 ccw(c7055.46,4591.31) v1@7039.24,4575.09 ; v1@7028.64,4572.26 ccw(c7019.25,4581.65) 7032.52,4581.65 ccw(c7045.8,4581.65) v1@7036.41,4572.26
  MidLayer2 w4: v1(6115,4065) 6138.37,4065 6148.37,4055 6225.23,4055 6253.85,4026.37 6375.88,4026.37 6390.88,4041.37 6510,4041.37 6518.63,4041.37 6548.63,4041.37 6565,4025 6606.96,3983.04 6736.96,3983.04 6782,3938 6901.48,3938 v1(6930.19,3966.71) ; v1@6118.89,4061.11 cw(c6128.28,4051.72) 6128.28,4065 cw(c6128.28,4078.28) v1@6118.89,4068.89 ; v1@6121.72,4058.28 cw(c6137.93,4042.06) 6137.93,4065 cw(c6137.93,4087.93) v1@6121.72,4071.72 ; v1@6920.69,3966.71 cw(c6897.76,3966.71) 6913.97,3950.49 cw(c6930.19,3934.27) v1@6930.19,3957.21 ; v1@6924.69,3966.71 cw(c6911.41,3966.71) 6920.8,3957.32 cw(c6930.19,3947.93) v1@6930.19,3961.21 ; v1(7032.52,4568.37) 7199.86,4568.37 7215.19,4553.04 7215.19,4512.04 7231.86,4495.37 7253.19,4495.37 7335.52,4577.71 7524.61,4577.71 7577.94,4524.37 v2(7692.52,4524.37) ; v1@7036.41,4564.49 cw(c7045.8,4555.1) 7045.8,4568.37 cw(c7045.8,4581.65) v1@7036.41,4572.26 ; v1@7039.24,4561.66 cw(c7055.46,4545.44) 7055.46,4568.37 cw(c7055.46,4591.31) v1@7039.24,4575.09 ; v2@7684.74,4516.59 ccw(c7665.96,4497.82) 7665.96,4524.37 ccw(c7665.96,4550.93) v2@7684.74,4532.15 ; v2@7687.57,4519.42 ccw(c7675.62,4507.47) 7675.62,4524.37 ccw(c7675.62,4541.27) v2@7687.57,4529.32
  Bottom Layer w4: v3@5548.13,4103.79 cw(c5549.71,4085.75) 5561.35,4099.62 ; v3@5554.95,4111.91 ccw(c5572.99,4113.49) 5561.35,4099.62 ; v1(6115,4065) 6115,4079.59 6101.77,4092.81 6013.53,4092.81 6008.11,4087.4 5924.74,4087.4 5920,4087.4 5910,4087.4 5703.9,4087.4 5684.48,4087.4 5610.36,4087.4 5590.86,4087.4 cw(c5590.86,4129.13) 5561.35,4099.62 ; v1(6947.19,4352.37) 7016.19,4421.37 7016.19,4451.04 7040.19,4475.04 7040.19,4560.71 v1(7032.52,4568.37) ; v1@6947.19,4357.87 ccw(c6947.19,4371.15) 6956.58,4361.76 ccw(c6965.97,4352.37) v1@6952.69,4352.37 ; v1@6947.19,4361.87 ccw(c6947.19,4384.81) 6963.41,4368.59 ccw(c6979.63,4352.37) v1@6956.69,4352.37 ; v1@7025.81,4561.66 cw(c6991.08,4526.93) 7040.19,4526.93 ; v1@7028.64,4564.49 cw(c7000.74,4536.59) 7040.19,4536.59 ; v1@7031.46,4567.31 cw(c7010.4,4546.25) 7040.19,4546.25 ; v1@7034.29,4570.14 cw(c7020.05,4555.9) 7040.19,4555.9
DB_MEM.BUS_D4: U7.H5 U8.T23 U12.8 U16.13 U61.42 | length 6009.3
  Top Layer w4: U8.T23@5764.02,4084.07 cw(c5764.02,4065.97) 5776.82,4078.77 cw(c5789.62,4091.57) U8.T23@5771.52,4091.57 ; U8.T23@5764.02,4084.23 cw(c5764.02,4066.51) 5776.55,4079.04 cw(c5789.08,4091.57) U8.T23@5771.36,4091.57 ; U8.T23@5764.02,4091.57 v3(5783.7,4071.89) ; v1@6183.47,2609.99 cw(c6167.26,2593.77) 6190.19,2593.77 cw(c6213.13,2593.77) v1@6196.91,2609.99 ; v1@6186.3,2612.82 cw(c6176.91,2603.43) 6190.19,2603.43 cw(c6203.47,2603.43) v1@6194.08,2612.82 ; v1(6190.19,2616.71) 6190.19,2583.37 6148.52,2541.71 6148.52,2408.37 6205.87,2351.03 U61.42@6351.49,2351.03 ; U61.42@6335.91,2348.2 ccw(c6329.08,2341.37) 6329.08,2351.03 ccw(c6329.08,2360.69) U61.42@6335.91,2353.86 ; U12.8@6845.59,3953.98 6856.86,3953.98 6856.86,3958.37 v1@6891.52,3958.37 ; U16.13@6845.59,4592.76 6957.48,4592.76 v1(6981.86,4568.37) ; U12.8@6863.15,3953.98 cw(c6873.22,3944.66) 6873.22,3958.37 ; U12.8@6864.82,3958.37 cw(c6864.82,3926.33) v1@6887.47,3948.99 ; U12.8@6866.08,3951.26 cw(c6882.37,3936.18) 6882.37,3958.37 ; U16.13@6868.81,4587.1 cw(c6882.46,4573.44) 6882.46,4592.76 cw(c6882.46,4612.07) U16.13@6868.81,4598.41 ; U12.8@6869.02,3948.54 cw(c6891.52,3927.71) v1@6891.52,3958.37 ; 6874.47,3958.37 cw(c6874.47,3935.99) v1@6890.3,3951.82 ; 6877.69,3958.37 ccw(c6877.69,3972.2) v1@6887.47,3962.43 ; v1(6894.19,3955.71) v1@6891.52,3958.37 ; v1@6972.36,4568.37 ccw(c6949.42,4568.37) 6965.64,4584.59 ccw(c6981.86,4600.81) v1@6981.86,4577.87 ; v1@6976.36,4568.37 ccw(c6963.08,4568.37) 6972.47,4577.76 ccw(c6981.86,4587.15) v1@6981.86,4573.87 ; 5770.9,4084.69 cw(c5758.09,4071.89) 5776.2,4071.89 ccw(c5758.09,4071.89) 5770.9,4084.69 ; 5770.9,4084.69 ccw(c5783.7,4097.5) 5783.7,4079.39 cw(c5783.7,4097.5) 5770.9,4084.69
  Top Layer w8: v2(7692.52,4445.63) U7.H5@7712.2,4465.32 ; v2@7692.52,4454.63 ccw(c7692.52,4476.36) 7707.88,4460.99 ccw(c7723.25,4445.63) v2@7701.52,4445.63 ; U7.H5@7706.2,4465.32 cw(c7691.72,4465.32) 7701.96,4455.07 cw(c7712.2,4444.83) U7.H5@7712.2,4459.32
  MidLayer1 w4: v3(5783.7,4071.89) 5861.38,4071.89 5910,4071.89 5920,4071.89 5924.74,4071.89 5981.86,4071.89 5990.19,4063.56 6001.25,4052.5 6046.42,4052.5 6077.04,4021.87 6149.44,4021.87 6187.62,3983.7 6187.62,3953.28 6265.19,3875.71 ; v3@5788.89,4066.7 cw(c5801.43,4054.16) 5801.43,4071.89 cw(c5801.43,4089.62) v3@5788.89,4077.08 ; v3@5789,4066.59 cw(c5801.81,4053.78) 5801.81,4071.89 cw(c5801.81,4090) v3@5789,4077.19 ; v1@6183.47,2623.43 ccw(c6167.26,2639.64) 6190.19,2639.64 ccw(c6213.13,2639.64) v1@6196.91,2623.43 ; v1@6186.3,2620.6 ccw(c6176.91,2629.99) 6190.19,2629.99 ccw(c6203.47,2629.99) v1@6194.08,2620.6 ; v1(6190.19,2616.71) 6190.19,2683.37 6244.86,2738.04 6244.86,2914.02 6285.86,2955.02 6285.86,3022.04 6273.52,3034.37 6273.52,3069.69 6281.19,3077.35 6281.19,3195.02 6285,3198.83 6287.19,3201.02 6287.19,3349.71 6299.52,3362.04 6299.52,3391.71 6220,3471.23 6220,3504.85 6306.43,3591.28 6306.86,3591.71 6306.86,3742.02 6281.86,3767.02 6281.86,3800.04 6265.19,3816.71 v1(6265.19,3859.04) 6265.19,3875.71 ; v1@6258.47,3852.32 cw(c6242.26,3836.11) 6265.19,3836.11 cw(c6288.13,3836.11) v1@6271.91,3852.32 ; v1@6260.35,3867.22 ccw(c6255.32,3875.71) 6265.19,3875.71 ; v1@6261.3,3855.15 cw(c6251.91,3845.76) 6265.19,3845.76 cw(c6278.47,3845.76) v1@6269.08,3855.15 ; v1@6270.03,3867.22 cw(c6275.06,3875.71) 6265.19,3875.71 ; v1(6894.19,3955.71) 6940.19,4001.71 6940.19,4052.35 6958.86,4071.02 6958.86,4224.37 6923.52,4259.71 v1(6923.52,4293.04) ; v1@6894.19,3961.21 ccw(c6894.19,3974.49) 6903.58,3965.1 ccw(c6912.97,3955.71) v1@6899.69,3955.71 ; v1@6894.19,3965.21 ccw(c6894.19,3988.14) 6910.41,3971.93 ccw(c6926.63,3955.71) v1@6903.69,3955.71 ; v1@6916.81,4286.32 cw(c6900.59,4270.11) 6923.52,4270.11 cw(c6946.46,4270.11) v1@6930.24,4286.32 ; v1@6919.64,4289.15 cw(c6910.25,4279.76) 6923.52,4279.76 cw(c6936.8,4279.76) v1@6927.41,4289.15
  MidLayer2 w4: v1(6998.52,4433.37) 7261.47,4433.37 7287.8,4459.71 7333.19,4459.71 7611.19,4459.71 v1(7620.86,4450.04) ; v1@7002.41,4429.49 cw(c7011.8,4420.1) 7011.8,4433.37 cw(c7011.8,4446.65) v1@7002.41,4437.26 ; v1@7005.24,4426.66 cw(c7021.46,4410.44) 7021.46,4433.37 cw(c7021.46,4456.31) v1@7005.24,4440.09
  Bottom Layer w4: v1(6265.19,3859.04) 6313.52,3907.37 6368.17,3907.37 6419.5,3958.71 6567.84,3958.71 6609.84,3916.71 6855.19,3916.71 v1(6894.19,3955.71) ; v1@6265.19,3864.54 ccw(c6265.19,3877.82) 6274.58,3868.43 ccw(c6283.97,3859.04) v1@6270.69,3859.04 ; v1@6265.19,3868.54 ccw(c6265.19,3891.48) 6281.41,3875.26 ccw(c6297.63,3859.04) v1@6274.69,3859.04 ; v1@6884.69,3955.71 cw(c6861.76,3955.71) 6877.97,3939.49 cw(c6894.19,3923.27) v1@6894.19,3946.21 ; v1@6888.69,3955.71 cw(c6875.41,3955.71) 6884.8,3946.32 cw(c6894.19,3936.93) v1@6894.19,3950.21 ; v1@6916.81,4299.76 ccw(c6900.59,4315.98) 6923.52,4315.98 ccw(c6946.46,4315.98) v1@6930.24,4299.76 ; v1@6919.64,4296.93 ccw(c6910.25,4306.32) 6923.52,4306.32 ccw(c6936.8,4306.32) v1@6927.41,4296.93 ; v1(6923.52,4293.04) 6923.52,4383.37 6986.02,4445.87 ; v1@6981.86,4558.87 cw(c6981.86,4535.94) 6998.07,4552.16 cw(c7014.29,4568.37) v1@6991.36,4568.37 ; v1@6981.86,4562.87 cw(c6981.86,4549.6) 6991.25,4558.99 cw(c7000.64,4568.37) v1@6987.36,4568.37 ; v1(6981.86,4568.37) 7031.86,4518.37 7031.86,4491.71 6986.02,4445.87 ; v1(6998.52,4433.37) 6986.02,4445.87 ; v1(7620.86,4450.04) 7628.19,4450.04 7632.6,4445.63 v2(7692.52,4445.63) ; v1@7621.92,4451.1 ccw(c7635.13,4464.31) 7635.13,4445.63 ; v1@7624.75,4453.93 ccw(c7644.78,4473.97) 7644.78,4445.63 ; v1@7627.57,4443.32 cw(c7633.14,4437.75) 7633.14,4445.63 ; v1@7627.57,4456.76 ccw(c7654.44,4483.62) 7654.44,4445.63 ; v2@7684.74,4437.85 ccw(c7665.96,4419.07) 7665.96,4445.63 ccw(c7665.96,4472.19) v2@7684.74,4453.41 ; v2@7687.57,4440.68 ccw(c7675.62,4428.73) 7675.62,4445.63 ccw(c7675.62,4462.53) v2@7687.57,4450.58
DB_MEM.BUS_D5: U7.E5 U8.U23 U12.10 U16.14 U61.43 | length 6965.3
  Top Layer w4: U8.U23@5764.02,4044.7 cw(c5764.02,4026.6) 5776.82,4039.4 cw(c5789.62,4052.2) U8.U23@5771.52,4052.2 ; U8.U23@5764.02,4044.86 cw(c5764.02,4027.14) 5776.55,4039.67 cw(c5789.08,4052.2) U8.U23@5771.36,4052.2 ; U8.U23@5764.02,4052.2 v3(5783.7,4032.52) ; U61.43@6351.93,2370.72 6411.18,2370.72 6415.19,2366.71 6442.86,2366.71 6452.19,2376.04 6452.19,2470 6465.19,2483 v1(6465.19,2617.71) ; U61.43@6367.95,2367.89 cw(c6374.78,2361.06) 6374.78,2370.72 cw(c6374.78,2380.37) U61.43@6367.95,2373.54 ; v1@6458.47,2610.99 cw(c6442.26,2594.77) 6465.19,2594.77 cw(c6488.13,2594.77) v1@6471.91,2610.99 ; v1@6461.3,2613.82 cw(c6451.91,2604.43) 6465.19,2604.43 cw(c6478.47,2604.43) v1@6469.08,2613.82 ; v1@6781.86,3957.21 cw(c6781.86,3934.27) 6798.07,3950.49 cw(c6814.29,3966.71) v1@6791.36,3966.71 ; v1@6781.86,3961.21 cw(c6781.86,3947.93) 6791.25,3957.32 cw(c6800.64,3966.71) v1@6787.36,3966.71 ; v1(6781.86,3966.71) 6806.86,3941.71 6806.86,3898.98 6814.86,3890.98 ; U12.10@6820.93,3887.29 ccw(c6814.86,3884.14) 6814.86,3890.98 ; U12.10@6820.93,3894.67 cw(c6814.86,3897.83) 6814.86,3890.98 ; U12.10@6845.59,3890.98 6814.86,3890.98 ; U16.14@6845.59,4561.26 6863.15,4561.26 6875.7,4548.71 ; U16.14@6863.64,4553.27 cw(c6864.6,4537.61) 6875.7,4548.71 ; U16.14@6871.13,4560.77 ccw(c6886.78,4559.8) 6875.7,4548.71 ; v1@6963.47,3948.43 ccw(c6947.26,3964.64) 6970.19,3964.64 ccw(c6993.13,3964.64) v1@6976.91,3948.43 ; v1@6966.3,3945.6 ccw(c6956.91,3954.99) 6970.19,3954.99 ccw(c6983.47,3954.99) v1@6974.08,3945.6 ; v1(6970.19,3941.71) 6970.19,4011.71 6948.52,4033.37 6948.52,4051.37 7023.52,4126.37 7023.52,4257.04 7056.86,4290.37 7056.86,4421.37 7032.19,4446.04 7032.19,4475.37 7040.19,4483.37 7040.19,4533.37 7024.86,4548.71 6875.7,4548.71 ; 5770.9,4045.32 cw(c5758.09,4032.52) 5776.2,4032.52 ccw(c5758.09,4032.52) 5770.9,4045.32 ; 5770.9,4045.32 ccw(c5783.7,4058.13) 5783.7,4040.02 cw(c5783.7,4058.13) 5770.9,4045.32
  Top Layer w8: v2(7810.63,4445.63) U7.E5@7830.32,4465.32 ; v2@7810.63,4454.63 ccw(c7810.63,4476.36) 7825.99,4460.99 ccw(c7841.36,4445.63) v2@7819.63,4445.63 ; U7.E5@7824.32,4465.32 cw(c7809.83,4465.32) 7820.07,4455.07 cw(c7830.32,4444.83) U7.E5@7830.32,4459.32
  MidLayer1 w4: v3(5783.7,4032.52) 5861.38,4032.52 5910,4032.52 5920,4032.52 6002.73,4032.52 6022.75,4012.5 6060,4012.5 6061.37,4013.87 6146.13,4013.87 6179.62,3980.38 6179.62,3928.28 v1(6215.19,3892.71) ; v3@5788.89,4027.33 cw(c5801.43,4014.79) 5801.43,4032.52 cw(c5801.43,4050.25) v3@5788.89,4037.71 ; v1@6205.69,3892.71 ccw(c6182.76,3892.71) 6198.97,3908.93 ccw(c6215.19,3925.14) v1@6215.19,3902.21 ; v1@6209.69,3892.71 ccw(c6196.41,3892.71) 6205.8,3902.1 ccw(c6215.19,3911.49) v1@6215.19,3898.21 ; v1(6465.19,2617.71) 6487.19,2639.71 6487.19,2662.38 6506.86,2682.05 6506.86,2819.69 6515.19,2828.02 6515.19,3155.71 6556.86,3197.37 6556.86,3247.37 6540.19,3264.04 6540.19,3291.71 6606.86,3358.37 6606.86,3994.04 6664.19,4051.37 6697.19,4051.37 v1(6781.86,3966.71) ; v1@6465.19,2623.21 ccw(c6465.19,2636.49) 6474.58,2627.1 ccw(c6483.97,2617.71) v1@6470.69,2617.71 ; v1@6465.19,2627.21 ccw(c6465.19,2650.14) 6481.41,2633.93 ccw(c6497.63,2617.71) v1@6474.69,2617.71 ; v1@6772.36,3966.71 ccw(c6749.42,3966.71) 6765.64,3982.93 ccw(c6781.86,3999.14) v1@6781.86,3976.21 ; v1@6776.36,3966.71 ccw(c6763.08,3966.71) 6772.47,3976.1 ccw(c6781.86,3985.49) v1@6781.86,3972.21 ; v1@7675.14,4171.76 ccw(c7658.92,4187.98) 7681.86,4187.98 ccw(c7704.79,4187.98) v1@7688.57,4171.76 ; v1@7677.97,4168.93 ccw(c7668.58,4178.32) 7681.86,4178.32 ccw(c7695.14,4178.32) v1@7685.75,4168.93 ; v1(7681.86,4165.04) 7681.86,4233.14 7668,4247 7668,4466.54 7683.28,4481.82 7803.18,4481.82 7810.63,4474.37 v2(7810.63,4445.63) ; v2@7802.85,4453.41 ccw(c7784.07,4472.19) 7810.63,4472.19 ccw(c7837.19,4472.19) v2@7818.41,4453.41 ; v2@7805.68,4450.58 ccw(c7793.73,4462.53) 7810.63,4462.53 ccw(c7827.53,4462.53) v2@7815.58,4450.58 ; 5801.81,4032.52 cw(c5801.81,4050.63) 5789,4037.82 ccw(c5801.81,4050.63) 5801.81,4032.52 ; 5801.81,4032.52 ccw(c5801.81,4014.41) 5789,4027.22 cw(c5801.81,4014.41) 5801.81,4032.52
  Bottom Layer w4: v1(6215.19,3892.71) 6215.19,3898.71 6231.86,3915.37 ; v1@6215.19,3902.21 ccw(c6215.19,3910.66) 6221.17,3904.68 ; v1@6216.68,3892.91 cw(c6229.69,3894.64) 6220.41,3903.93 ; v1@6220.64,3893.43 cw(c6239.8,3895.99) 6226.13,3909.65 ; v1@6224.61,3893.96 cw(c6249.9,3897.33) 6231.86,3915.37 ; v1@6775.14,3959.99 ccw(c6758.92,3943.77) 6758.92,3966.71 ccw(c6758.92,3989.64) v1@6775.14,3973.43 ; v1@6777.97,3962.82 ccw(c6768.58,3953.43) 6768.58,3966.71 ccw(c6768.58,3979.99) v1@6777.97,3970.6 ; v1@6785.75,3962.82 cw(c6795.14,3953.43) 6795.14,3966.71 cw(c6795.14,3979.99) v1@6785.75,3970.6 ; v1@6788.57,3959.99 cw(c6804.79,3943.77) 6804.79,3966.71 cw(c6804.79,3989.64) v1@6788.57,3973.43 ; v1@6963.47,3948.43 ccw(c6947.26,3964.64) 6970.19,3964.64 ccw(c6993.13,3964.64) v1@6976.91,3948.43 ; v1@6966.3,3945.6 ccw(c6956.91,3954.99) 6970.19,3954.99 ccw(c6983.47,3954.99) v1@6974.08,3945.6 ; v1(6970.19,3941.71) 6970.19,3990.19 6961.37,3999.01 6929.56,3999.01 6913.52,4015.04 6865.19,3966.71 ; v1@7672.36,4165.04 cw(c7649.42,4165.04) 7665.64,4148.82 cw(c7681.86,4132.61) v1@7681.86,4155.54 ; v1@7676.36,4165.04 cw(c7663.08,4165.04) 7672.47,4155.65 cw(c7681.86,4146.26) v1@7681.86,4159.54 ; v1(7681.86,4165.04) 7633.52,4116.71 7426.51,4116.71 7401.51,4091.71 7206.86,4091.71 7173.52,4058.37 7140.19,4058.37 7131.86,4066.71 7131.86,4083.37 7114.86,4100.37 6993.5,4100.37 6926.82,4033.69 6926.82,4028.34 6865.19,3966.71 ; 6231.86,3915.37 6364.86,3915.37 6416.19,3966.71 v1(6781.86,3966.71) 6865.19,3966.71
DB_MEM.BUS_D6: U7.H6 U8.U24 U12.11 U16.15 U61.45 | length 6808.1
  Top Layer w4: v1@6114.02,3912.71 ccw(c6091.09,3912.71) 6107.31,3928.93 ccw(c6123.52,3945.14) v1@6123.52,3922.21 ; v1@6118.02,3912.71 ccw(c6104.75,3912.71) 6114.14,3922.1 ccw(c6123.52,3931.49) v1@6123.52,3918.21 ; v1(6123.52,3912.71) 6092.5,3943.73 6092.5,3990.73 6091.19,3992.04 6073.52,4009.71 5989,4009.71 5960.88,4009.71 5942.24,4028.34 5940.19,4028.34 5924.74,4028.34 5920,4028.34 5910,4028.34 5843.27,4028.34 ; v1(6298.52,2391.71) 6316.9,2410.09 U61.45@6351.93,2410.09 ; v1@6298.52,2397.21 ccw(c6298.52,2410.49) 6307.91,2401.1 ccw(c6317.3,2391.71) v1@6304.02,2391.71 ; v1@6298.52,2401.21 ccw(c6298.52,2424.14) 6314.74,2407.93 ccw(c6330.96,2391.71) v1@6308.02,2391.71 ; U61.45@6335.91,2407.26 ccw(c6329.08,2400.43) 6329.08,2410.09 ccw(c6329.08,2419.74) U61.45@6335.91,2412.91 ; U12.11@6845.59,3859.49 6900,3859.49 6905.22,3864.71 v1(6954.52,3864.71) v1@6948.19,3858.37 ; U16.15@6845.59,4529.76 6848.52,4529.76 6858.8,4540.04 7022.21,4540.04 7032.19,4530.06 7032.19,4486.69 7024.19,4478.69 7024.19,4425.71 v1(7037.86,4412.04) ; U16.15@6854.66,4538.25 cw(c6858.99,4533.92) 6858.99,4540.04 ; U16.15@6857.49,4535.42 cw(c6868.65,4524.27) 6868.65,4540.04 ; U16.15@6860.32,4532.59 cw(c6878.3,4514.61) 6878.3,4540.04 ; U16.15@6863.15,4529.76 cw(c6887.96,4504.95) 6887.96,4540.04 ; U16.15@6865.98,4526.94 cw(c6897.62,4495.3) 6897.62,4540.04 ; U12.11@6868.81,3853.83 cw(c6882.46,3840.18) 6882.46,3859.49 cw(c6882.46,3878.8) U12.11@6868.81,3865.15 ; U16.15@6868.81,4524.11 cw(c6907.27,4485.64) 6907.27,4540.04 ; v1@6947.81,3857.99 ccw(c6931.59,3841.77) 6931.59,3864.71 ccw(c6931.59,3887.64) v1@6947.81,3871.43 ; v1@6950.64,3860.82 ccw(c6941.25,3851.43) 6941.25,3864.71 ccw(c6941.25,3877.99) v1@6950.64,3868.6 ; 5815.92,4039.67 ccw(c5843.27,4067.02) 5843.27,4028.34 ; 5815.92,4039.67 ccw(c5843.27,4067.02) 5843.27,4028.34 ; 5815.92,4039.67 cw(c5828.45,4052.2) 5810.73,4052.2 ccw(c5828.45,4052.2) 5815.92,4039.67 ; 5815.92,4039.67 ccw(c5803.39,4027.14) 5803.39,4044.86 cw(c5803.39,4027.14) 5815.92,4039.67
  Top Layer w8: v2(7692.52,4406.26) U7.H6@7712.2,4425.94 ; v2@7692.52,4415.26 ccw(c7692.52,4436.99) 7707.88,4421.62 ccw(c7723.25,4406.26) v2@7701.52,4406.26 ; U7.H6@7706.2,4425.94 cw(c7691.72,4425.94) 7701.96,4415.7 cw(c7712.2,4405.46) U7.H6@7712.2,4419.94
  MidLayer1 w4: v1@6298.52,2382.21 cw(c6298.52,2359.27) 6314.74,2375.49 cw(c6330.96,2391.71) v1@6308.02,2391.71 ; v1@6298.52,2386.21 cw(c6298.52,2372.93) 6307.91,2382.32 cw(c6317.3,2391.71) v1@6304.02,2391.71 ; v1(6298.52,2391.71) 6340.19,2350.04 6497.19,2350.04 6537.19,2390.04 6537.19,2472.04 6733.86,2668.71 6733.86,2760.37 7131.86,3158.37 7131.86,3488.04 v1(7223.52,3579.71) ; v1(6954.52,3864.71) 6954.52,3871.71 7049.52,3966.71 v1(7049.52,4158.04) 7073.52,4182.04 7073.52,4368.04 7029.52,4412.04 v1(7037.86,4412.04) ; v1@7039.36,4412.04 ccw(c7063.1,4412.04) 7046.31,4395.25 ; v1@7042.81,4151.32 cw(c7026.59,4135.11) 7049.52,4135.11 cw(c7072.46,4135.11) v1@7056.24,4151.32 ; v1@7043.36,4412.04 ccw(c7076.75,4412.04) 7053.14,4388.43 ; v1@7045.64,4154.15 cw(c7036.25,4144.76) 7049.52,4144.76 cw(c7062.8,4144.76) v1@7053.41,4154.15 ; v1@7047.36,4412.04 ccw(c7090.41,4412.04) 7059.97,4381.6 ; v1@7049.52,4163.54 ccw(c7049.52,4176.82) 7058.91,4167.43 ccw(c7068.3,4158.04) v1@7055.02,4158.04 ; v1@7049.52,4167.54 ccw(c7049.52,4190.48) 7065.74,4174.26 ccw(c7081.96,4158.04) v1@7059.02,4158.04 ; v1@7214.02,3579.71 cw(c7191.09,3579.71) 7207.31,3563.49 cw(c7223.52,3547.27) v1@7223.52,3570.21 ; v1@7218.02,3579.71 cw(c7204.75,3579.71) 7214.14,3570.32 cw(c7223.52,3560.93) v1@7223.52,3574.21
  MidLayer2 w4: v1@6948.34,3857.5 cw(c6936.8,3844.04) 6954.52,3844.04 ; v1@6950.94,3860.53 cw(c6944.26,3852.74) 6954.52,3852.74 cw(c6964.79,3852.74) v1@6958.11,3860.53 ; v1(6954.52,3864.71) 6954.52,3844.04 ; v1@6960.71,3857.5 ccw(c6972.25,3844.04) 6954.52,3844.04 ; v1@7047.76,4159.81 cw(c7064.41,4143.15) 7064.41,4166.71 ; v1(7049.52,4158.04) 7058.19,4166.71 7306.86,4166.71 7431.86,4291.71 7541.52,4291.71 7656.08,4406.26 v2(7692.52,4406.26) ; v1@7050.58,4156.98 cw(c7074.07,4133.5) 7074.07,4166.71 ; v1@7053.41,4154.15 cw(c7083.73,4123.84) 7083.73,4166.71 ; v1@7056.24,4151.32 cw(c7093.38,4114.18) 7093.38,4166.71 ; v1(7223.52,3579.71) 7256.86,3613.04 7256.86,3741.71 7215.19,3783.37 7015.19,3783.37 6954.52,3844.04 ; v1@7223.52,3585.21 ccw(c7223.52,3598.49) 7232.91,3589.1 ccw(c7242.3,3579.71) v1@7229.02,3579.71 ; v1@7223.52,3589.21 ccw(c7223.52,3612.14) 7239.74,3595.93 ccw(c7255.96,3579.71) v1@7233.02,3579.71 ; v2@7684.74,4398.48 ccw(c7665.96,4379.7) 7665.96,4406.26 ccw(c7665.96,4432.82) v2@7684.74,4414.04 ; v2@7687.57,4401.31 ccw(c7675.62,4389.36) 7675.62,4406.26 ccw(c7675.62,4423.16) v2@7687.57,4411.21
  Bottom Layer w4: v1@6123.52,3903.21 cw(c6123.52,3880.27) 6139.74,3896.49 cw(c6155.96,3912.71) v1@6133.02,3912.71 ; v1@6123.52,3907.21 cw(c6123.52,3893.93) 6132.91,3903.32 cw(c6142.3,3912.71) v1@6129.02,3912.71 ; v1(6123.52,3912.71) 6156.86,3879.37 6156.86,3800.04 6190.19,3766.71 6248.52,3766.71 6262.21,3766.71 6300.5,3805 6303.88,3808.37 6398.52,3808.37 6448.52,3758.37 6499.86,3758.37 6558.19,3816.71 6780.52,3816.71 6781.86,3818.04 6849.86,3818.04 6896.52,3864.71 v1(6954.52,3864.71) ; v1@6947.81,3857.99 ccw(c6931.59,3841.77) 6931.59,3864.71 ccw(c6931.59,3887.64) v1@6947.81,3871.43 ; v1@6950.64,3860.82 ccw(c6941.25,3851.43) 6941.25,3864.71 ccw(c6941.25,3877.99) v1@6950.64,3868.6
DB_MEM.BUS_D7: U7.E6 U8.G24 U12.13 U16.16 U61.46 | length 7046.9
  Top Layer w4: v1@6069.14,4893.32 cw(c6058.55,4882.74) 6073.52,4882.74 ; 6073.52,4871.47 cw(c6104.42,4871.47) v1@6082.57,4893.32 ; 6073.52,4881.13 cw(c6094.77,4881.13) v1@6079.75,4896.15 ; v1(6075.86,4900.04) 6073.52,4897.71 6073.52,4836.37 6136.52,4773.37 6136.52,4746.37 6098.52,4708.37 6098.52,4675.04 6106.86,4666.71 6106.86,4633.37 6136.86,4603.37 6136.86,4525.04 6086.86,4475.04 6058.19,4475.04 6041.52,4458.37 5948.92,4458.37 5937.52,4469.77 5924.74,4469.77 5920,4469.77 5910,4469.77 5843.27,4469.77 ; U61.46@6351.93,2429.77 6378.52,2429.77 6383.25,2425.04 v1(6390.19,2425.04) ; U61.46@6355.84,2429.77 cw(c6355.84,2390.69) v1@6383.47,2418.32 ; U61.46@6365.49,2429.77 cw(c6365.49,2400.34) v1@6386.3,2421.15 ; U61.46@6367.95,2426.94 cw(c6374.78,2420.11) 6374.78,2429.77 cw(c6374.78,2439.43) U61.46@6367.95,2432.6 ; 6375.15,2429.77 cw(c6375.15,2410) v1@6389.13,2423.98 ; 6378.67,2429.77 ccw(c6378.67,2436.56) v1@6383.47,2431.76 ; U12.13@6845.59,3796.5 6919.74,3796.5 v1(6931.86,3784.37) 6973.52,3826.04 6973.52,3908.37 6948.52,3933.37 6948.52,4008.37 6940.19,4016.71 6940.19,4055.04 7005,4119.85 7005,4180 6985,4200 6985,4235 7031.86,4281.86 7031.86,4383.37 7016.19,4399.04 7016.19,4460 7006.86,4469.33 ; U16.16@6845.59,4498.27 6970,4498.27 6976.56,4491.71 v1(7006.86,4491.71) 7006.86,4469.33 ; U12.13@6868.81,3790.84 cw(c6882.46,3777.18) 6882.46,3796.5 cw(c6882.46,3815.81) U12.13@6868.81,3802.15 ; U16.16@6868.81,4492.61 cw(c6882.46,4478.95) 6882.46,4498.27 cw(c6882.46,4517.58) U16.16@6868.81,4503.92 ; v1@6931.86,3789.87 ccw(c6931.86,3803.15) 6941.25,3793.76 ccw(c6950.64,3784.37) v1@6937.36,3784.37 ; v1@6931.86,3793.87 ccw(c6931.86,3816.81) 6948.07,3800.59 ccw(c6964.29,3784.37) v1@6941.36,3784.37 ; v1@7000.14,4484.99 ccw(c6983.92,4468.77) 6983.92,4491.71 ccw(c6983.92,4514.64) v1@7000.14,4498.43 ; v1@7000.26,4484.87 cw(c6985.26,4469.33) 7006.86,4469.33 ; v1@7002.97,4487.82 ccw(c6993.58,4478.43) 6993.58,4491.71 ccw(c6993.58,4504.99) v1@7002.97,4495.6 ; v1@7003.04,4487.75 cw(c6994.35,4478.75) 7006.86,4478.75 cw(c7019.36,4478.75) v1@7010.68,4487.75 ; v1@7013.45,4484.87 ccw(c7028.45,4469.33) 7006.86,4469.33 ; 5815.92,4458.44 cw(c5843.27,4431.09) 5843.27,4469.77 ; 5815.92,4458.44 cw(c5843.27,4431.09) 5843.27,4469.77 ; 5815.92,4458.44 cw(c5803.39,4470.97) 5803.39,4453.25 ccw(c5803.39,4470.97) 5815.92,4458.44 ; 5815.92,4458.44 ccw(c5828.45,4445.91) 5810.73,4445.91 cw(c5828.45,4445.91) 5815.92,4458.44
  Top Layer w8: v2(7810.63,4406.26) U7.E6@7830.32,4425.94 ; v2@7810.63,4415.26 ccw(c7810.63,4436.99) 7825.99,4421.62 ccw(c7841.36,4406.26) v2@7819.63,4406.26 ; U7.E6@7824.32,4425.94 cw(c7809.83,4425.94) 7820.07,4415.7 cw(c7830.32,4405.46) U7.E6@7830.32,4419.94
  MidLayer1 w4: v1(6075.86,4900.04) 6681.86,4900.04 6732.19,4950.37 6867.94,4950.37 6940.19,4878.12 6940.19,4829.81 v1(6945,4825) ; v1@6079.75,4896.15 cw(c6089.14,4886.76) 6089.14,4900.04 cw(c6089.14,4913.32) v1@6079.75,4903.93 ; v1@6082.57,4893.32 cw(c6098.79,4877.11) 6098.79,4900.04 cw(c6098.79,4922.98) v1@6082.57,4906.76 ; v1@6380.69,2425.04 ccw(c6357.76,2425.04) 6373.97,2441.26 ccw(c6390.19,2457.48) v1@6390.19,2434.54 ; v1@6384.69,2425.04 ccw(c6371.41,2425.04) 6380.8,2434.43 ccw(c6390.19,2443.82) v1@6390.19,2430.54 ; v1(6390.19,2425.04) 6365.19,2450.04 6365.19,2553.37 6379.52,2567.71 6482.86,2567.71 6623.52,2708.37 6623.52,2858.37 6706.86,2941.71 6706.86,3384.37 6699.52,3391.71 6699.52,3442.71 6723.52,3466.71 6723.52,3483.37 6698.52,3508.37 6679.52,3508.37 6656.86,3531.04 6656.86,3627.71 6665.19,3636.04 6715.19,3636.04 6759.52,3591.71 6806.86,3591.71 6823.52,3608.37 6823.52,3645.04 6931.86,3753.37 v1(6931.86,3784.37) ; v1@6925.14,3777.66 cw(c6908.92,3761.44) 6931.86,3761.44 cw(c6954.79,3761.44) v1@6938.57,3777.66 ; v1@6927.97,3780.49 cw(c6918.58,3771.1) 6931.86,3771.1 cw(c6945.14,3771.1) v1@6935.75,3780.49 ; v1@6938.28,4831.72 ccw(c6933.68,4836.32) 6940.19,4836.32 ; 6940.19,4840.23 ccw(c6960.23,4840.23) v1@6946.06,4826.06 ; 6940.19,4849.89 ccw(c6969.89,4849.89) v1@6948.89,4828.89 ; 6940.19,4859.55 ccw(c6979.55,4859.55) v1@6951.72,4831.72
  MidLayer2 w4: v1(7006.86,4491.71) 7056.86,4491.71 7098.52,4450.04 7107.19,4441.37 7258.15,4441.37 7266.78,4450 7266.82,4450.04 7284.48,4467.71 7298.52,4467.71 7822.52,4467.71 7831.86,4458.37 7831.86,4425.04 ; v1@7010.75,4487.82 cw(c7020.14,4478.43) 7020.14,4491.71 cw(c7020.14,4504.99) v1@7010.75,4495.6 ; v1@7013.57,4484.99 cw(c7029.79,4468.77) 7029.79,4491.71 cw(c7029.79,4514.64) v1@7013.57,4498.43 ; v2(7810.63,4406.26) 7810.63,4408.37 7815.19,4408.37 7831.86,4425.04 ; v2@7811.05,4413.25 ccw(c7812.19,4432.13) 7825.57,4418.75 ; v2@7811.29,4417.24 ccw(c7812.91,4443.99) 7831.86,4425.04 ; v2@7821.63,4406.26 cw(c7842.28,4406.26) 7827.68,4420.86
  Bottom Layer w4: v1@6938.28,4818.28 cw(c6922.06,4802.06) 6945,4802.06 cw(c6967.93,4802.06) v1@6951.72,4818.28 ; v1@6941.11,4821.11 cw(c6931.72,4811.72) 6945,4811.72 cw(c6958.28,4811.72) v1@6948.89,4821.11 ; v1(6945,4825) 6945,4771.23 6966.02,4750.21 6966.02,4716.54 6956.52,4707.04 6956.52,4542.04 v1(7006.86,4491.71) ; v1@6997.36,4491.71 ccw(c6974.42,4491.71) 6990.64,4507.93 ccw(c7006.86,4524.14) v1@7006.86,4501.21 ; v1@7001.36,4491.71 ccw(c6988.08,4491.71) 6997.47,4501.1 ccw(c7006.86,4510.49) v1@7006.86,4497.21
